AutomationDirect Productivity Suite project: SD_Homing_Sensor (software 3.9.0 (26))
author: matt_cmelko
Rung notation: left to right = series (deeper-indented lines continue the line above), [a | b] = parallel branches, -- = plain wire, BOX.Pin = further input of the box above; 'quoted' = tag name, ? = field left empty; instruction and field names as stored in the project; options that are off are not listed.

HARDWARE
  EtherNet/IP device: Generic Client "ClearLink"
  Base 1 (1 slots)
    slot 0: P1-540

STRUCTURES
STRUCTURE 'Step Motor Status'
  AtTargetPosition : Boolean, strLength=15
  StepsActive : Boolean, strLength=15
  AtTargetVelocity : Boolean, strLength=15
  MoveDirection : Boolean, strLength=15
  InPosLimit : Boolean, strLength=15
  InNegLimit : Boolean, strLength=15
  InESTOPSensor : Boolean, strLength=15
  InHomeSensor : Boolean, strLength=15
  Homing : Boolean, strLength=15
  MotorInFault : Boolean, strLength=15
  Enabled : Boolean, strLength=15
  AtSoftLimits : Boolean, strLength=15
  PositionMove : Boolean, strLength=15
  HasHomed : Boolean, strLength=15
  HLFBON : Boolean, strLength=15
  HasTorqueMeasurement : Boolean, strLength=15
  ReadyToHome : Boolean, strLength=15
  ShutdownPresent : Boolean, strLength=15
  AddToPosAck : Boolean, strLength=15
  LoadPositionAck : Boolean, strLength=15
  LoadVelAck : Boolean, strLength=15
  ClearMotorFaultAck : Boolean, strLength=15
STRUCTURE 'Step Motor Shutdown'
  MCShutdownsPresent : Boolean, strLength=15
  MCPosLimit : Boolean, strLength=15
  MCNegLimit : Boolean, strLength=15
  MCSensorESTOP : Boolean, strLength=15
  MCSWESTOP : Boolean, strLength=15
  MCDisabled : Boolean, strLength=15
  MCSoftLimits : Boolean, strLength=15
  MCFollowerAxisFault : Boolean, strLength=15
  MCCmndFollowing : Boolean, strLength=15
  MCHomingNotReady : Boolean, strLength=15
  MotorFault : Boolean, strLength=15
  Reserved : Boolean, strLength=15
STRUCTURE 'Step Motor Output Reg'
  Enable : Boolean, strLength=15
  AbsolutelMoveFlag : Boolean, strLength=15
  HomingFlag : Boolean, strLength=15
  LoadPositionData : Boolean, strLength=15
  LoadVelocityData : Boolean, strLength=15
  SWESTOP : Boolean, strLength=15
  ClearAlerts : Boolean, strLength=15
  ClearMotorFault : Boolean, strLength=15
STRUCTURE 'Step and Dir Input Data'
  CommandedPosition : Array of Int32, dimensions=1, strLength=15
  CommandedVelocity : Array of Int32, dimensions=1, strLength=15
  TargetPosition : Array of Int32, dimensions=1, strLength=15
  TargetVelocity : Array of Int32, dimensions=1, strLength=15
  CapturedPosition : Array of Int32, dimensions=1, strLength=15
  MeasuredTorque : Array of Float32, dimensions=1, strLength=15
  MotorStatus : Step Motor Status, strLength=15
  MotorShutdowns : Step Motor Shutdown, strLength=15
STRUCTURE 'Step and Dir Output Data'
  MoveDistance : Array of Int32, dimensions=1, strLength=15
  VelocityLimit : Array of Int32, dimensions=1, strLength=15
  AccelerationLimit : Array of Int32, dimensions=1, strLength=15
  DecelerationLimit : Array of Int32, dimensions=1, strLength=15
  JogVelocity : Array of Int32, dimensions=1, strLength=15
  AddToPosition : Array of Int32, dimensions=1, strLength=15
  OutputReg : Step Motor Output Reg, strLength=15
STRUCTURE EncoderInputData
  PositionValue : Array of Int32, dimensions=1, strLength=15
  VelocityValue : Array of Int32, dimensions=1, strLength=15
  IndexPosition : Array of Int32, dimensions=1, strLength=15
  AlarmFlag : Array of Boolean, dimensions=1, strLength=15
  AddToPositionAck : Array of Boolean, dimensions=1, strLength=15
STRUCTURE 'IO Input Data'
  DIPValue : Array of Boolean, dimensions=13, strLength=15
  DIPStatus : Array of Boolean, dimensions=13, strLength=15
  AIPValue : Array of Int16, dimensions=4, strLength=15
  AIOPStatus : Array of Boolean, dimensions=5, strLength=15
  DOPStatus : Array of Boolean, dimensions=6, strLength=15
  CCIOInputValue : Array of Boolean, dimensions=64, strLength=15
  CCIOStatus : Array of Boolean, dimensions=64, strLength=15
  CCIOBoardCount : Array of Uint8, dimensions=1, strLength=15
STRUCTURE 'IO Output Data'
  AOPValue : Array of Int16, dimensions=1, strLength=15
  DOPValue : Array of Boolean, dimensions=6, strLength=15
  DOPPWM : Array of Uint8, dimensions=6, strLength=15
  CCIOOutputValue : Array of Boolean, dimensions=64, strLength=15
STRUCTURE 'ASCII INPUT'
  Status : Array of Boolean, dimensions=8, strLength=15
  OutputCharCount : Array of Int32, dimensions=1, strLength=15
  InputCharCount : Array of Int32, dimensions=1, strLength=15
  OutputSeqAck : Array of Int32, dimensions=1, strLength=15
  InputSize : Array of Int32, dimensions=1, strLength=15
  InputSeq : Array of Int32, dimensions=1, strLength=15
  InputData : Array of Uint8, dimensions=128, strLength=15
STRUCTURE 'ASCII Output'
  Config : Array of Boolean, dimensions=19, strLength=15
  InputSeqAck : Array of Int32, dimensions=1, strLength=15
  OutputSize : Array of Int32, dimensions=1, strLength=15
  OutputSeq : Array of Int32, dimensions=1, strLength=15
  OutputData : Array of Uint8, dimensions=128, strLength=15
STRUCTURE EncoderOutputData
  AddToPosn : Array of Int32, dimensions=1, strLength=15
STRUCTURE 'IO Output Data_1'
  AOPValue : Array of Int16, dimensions=1, strLength=15
  DOPValue : Array of Boolean, dimensions=6, strLength=15
  DOPPWM : Array of Uint8, dimensions=8, strLength=15
  CCIOOutputValue : Array of Boolean, dimensions=64, strLength=15

TAGS  (name : type @system ID = initial value)
  ClearLinkConnectionEnable : Boolean @C-000001
  CLstatusdescription : String(32) @STR-000001
  OutputData : Array[496] of Uint8 @AR1US8-000013
  InputData : Array[496] of Uint8 @AR1US8-000023
  'ClearLink Encoder Output' : EncoderOutputData @USTRUC-000068
  'ClearLink Encoder Input' : EncoderInputData @USTRUC-000069
  'ClearLink Motor0 Output' : Step and Dir Output Data @USTRUC-000070
  'ClearLink Motor1 Output' : Step and Dir Output Data @USTRUC-000072
  'ClearLink Motor2 Output' : Step and Dir Output Data @USTRUC-000074
  'ClearLink Motor3 Output' : Step and Dir Output Data @USTRUC-000076
  'ClearLink Motor3 Input' : Step and Dir Input Data @USTRUC-000078
  'ClearLink Motor2 Input' : Step and Dir Input Data @USTRUC-000081
  'ClearLink Motor1 Input' : Step and Dir Input Data @USTRUC-000084
  'ClearLink Motor0 Input' : Step and Dir Input Data @USTRUC-000087
  'ClearLink IO Input' : IO Input Data @USTRUC-000209
  'ClearLink IO Output' : IO Output Data @USTRUC-000210
  floatPlaceholder : Array[4] of Int32 @AR1S32-000267
  'ClearLink ASCII Input' : ASCII INPUT @USTRUC-000211
  'ClearLink ASCII Output' : ASCII Output @USTRUC-000212
  Begin_Homing : Boolean @C-000842
  Zero_Posn_After_Offset_Move : Boolean @C-000843
  ZeroPosnOneShot : Boolean @C-000845
  ClearLinkConnectionOnline : Boolean @C-000846

TASK 'Main Task'  (Run Every Scan)
// Program Name: SD_Homing_Sensor
// Program Description: This program is used to execute hardstop homing move and an offset move with a ClearPath-SD servo.
// See ladder comments below for descriptions on interacting with this example.
// Motor Required: One ClearPath-SD (Step & Direction) motor connected to ClearLink at connector M-0.
// Sensor Required: This example has been written to use a digital home sensor. Use a normally closed switch or NPN sensor wired to ClearLink's DI-6 input.
// Software Used: Productivity Suite (Version 3.9.0 was used to create this example).
// Controller Used: P1-540 was used to create this example.
// *******************************************************************************************************************************************************************************************
// BEFORE RUNNING THIS EXAMPLE, your ClearPath-SD motor must first be configured in MSP (ClearPath Motor Setup Program). See the ClearLink Software Object Data Reference for motor setup and configuration instructions: https://www.teknic.com/files/downloads/clearlink_ethernet-ip_object_reference.pdf.
// ***IMPORTANT*** FAILURE TO PROPERLY TUNE AND CONFIGURE YOUR CLEARPATH MOTOR BEFORE USE MAY RESULT IN UNEXPECTED MOTION, OR NO
// MOTION.
// *******************************************************************************************************************************************************************************************
// This example uses non-default ClearLink Configuration Data. Bit 0 of the Motor0Config register has been set to enable homing. Motor 0 Home Sensor has been set to 6, corresponding to input DI-6.
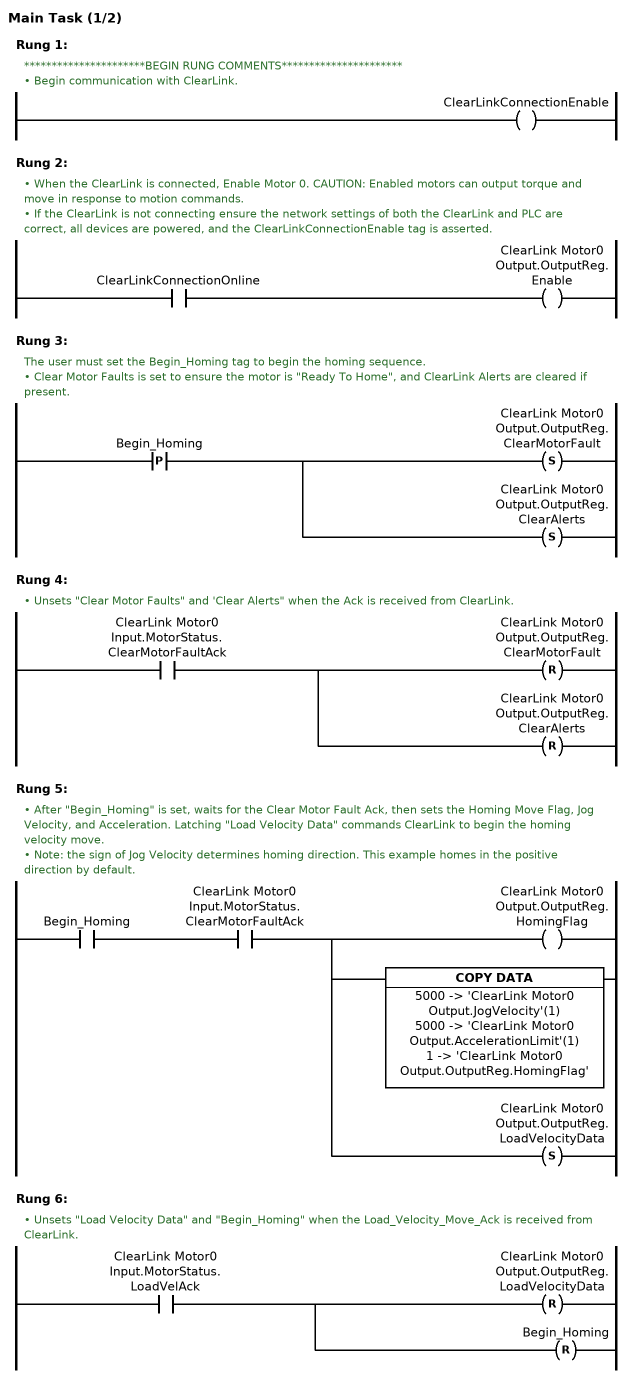
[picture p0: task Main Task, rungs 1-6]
Rung 1:
  // **********************BEGIN RUNG COMMENTS**********************
  // • Begin communication with ClearLink.
  OUT(ClearLinkConnectionEnable)
Rung 2:
  // • When the ClearLink is connected, Enable Motor 0. CAUTION: Enabled motors can output torque and move in response to motion commands.
  // • If the ClearLink is not connecting ensure the network settings of both the ClearLink and PLC are correct, all devices are powered, and the ClearLinkConnectionEnable tag is asserted.
  NO(ClearLinkConnectionOnline) OUT('ClearLink Motor0 Output.OutputReg.Enable')
Rung 3:
  // The user must set the Begin_Homing tag to begin the homing sequence.
  // • Clear Motor Faults is set to ensure the motor is "Ready To Home", and ClearLink Alerts are cleared if present.
  NOE(Begin_Homing, rising)
    [SET('ClearLink Motor0 Output.OutputReg.ClearMotorFault') | SET('ClearLink Motor0 Output.OutputReg.ClearAlerts')]
Rung 4:
  // • Unsets "Clear Motor Faults" and 'Clear Alerts" when the Ack is received from ClearLink.
  NO('ClearLink Motor0 Input.MotorStatus.ClearMotorFaultAck')
    [RST('ClearLink Motor0 Output.OutputReg.ClearMotorFault') | RST('ClearLink Motor0 Output.OutputReg.ClearAlerts')]
Rung 5:
  // • After "Begin_Homing" is set, waits for the Clear Motor Fault Ack, then sets the Homing Move Flag, Jog Velocity, and Acceleration. Latching "Load Velocity Data" commands ClearLink to begin the homing velocity move.
  // • Note: the sign of Jog Velocity determines homing direction. This example homes in the positive direction by default.
  NO(Begin_Homing) NO('ClearLink Motor0 Input.MotorStatus.ClearMotorFaultAck')
    [ OUT('ClearLink Motor0 Output.OutputReg.HomingFlag')
    | CPY(5000 -> 'ClearLink Motor0 Output.JogVelocity'(1), 5000 -> 'ClearLink Motor0 Output.AccelerationLimit'(1), 1 -> 'ClearLink Motor0 Output.OutputReg.HomingFlag')
    | SET('ClearLink Motor0 Output.OutputReg.LoadVelocityData') ]
Rung 6:
  // • Unsets "Load Velocity Data" and "Begin_Homing" when the Load_Velocity_Move_Ack is received from ClearLink.
  NO('ClearLink Motor0 Input.MotorStatus.LoadVelAck')
    [RST('ClearLink Motor0 Output.OutputReg.LoadVelocityData') | RST(Begin_Homing)]
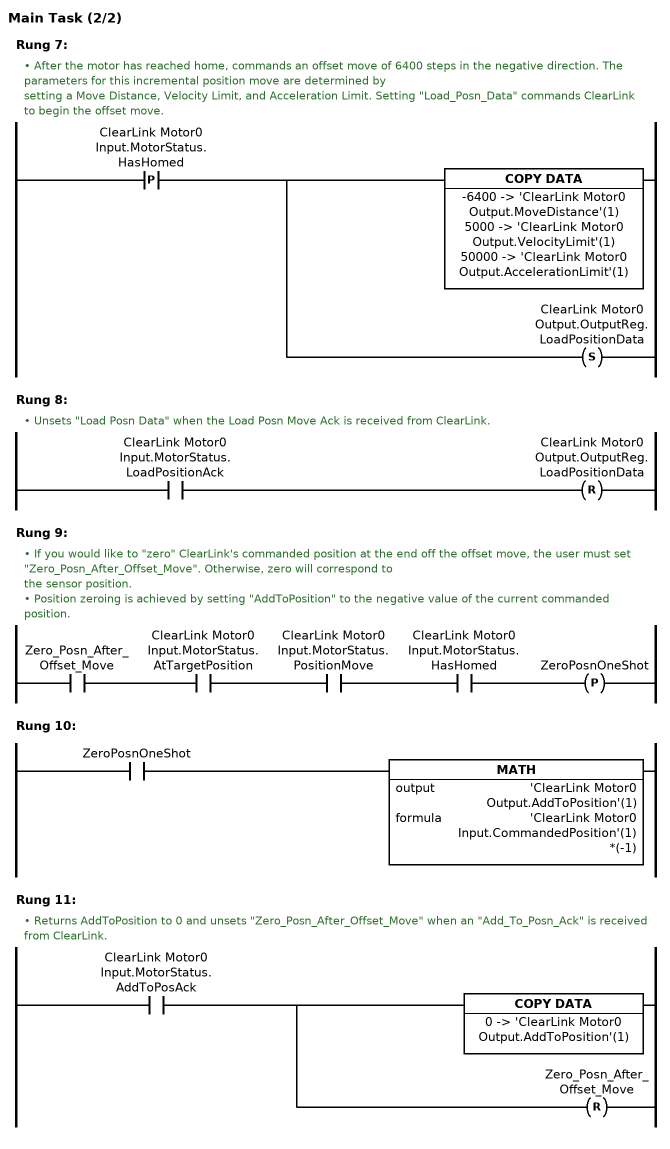
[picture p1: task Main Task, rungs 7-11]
Rung 7:
  // • After the motor has reached home, commands an offset move of 6400 steps in the negative direction. The parameters for this incremental position move are determined by
  // setting a Move Distance, Velocity Limit, and Acceleration Limit. Setting "Load_Posn_Data" commands ClearLink to begin the offset move.
  NOE('ClearLink Motor0 Input.MotorStatus.HasHomed', rising)
    [ CPY(-6400 -> 'ClearLink Motor0 Output.MoveDistance'(1), 5000 -> 'ClearLink Motor0 Output.VelocityLimit'(1), 50000 -> 'ClearLink Motor0 Output.AccelerationLimit'(1))
    | SET('ClearLink Motor0 Output.OutputReg.LoadPositionData') ]
Rung 8:
  // • Unsets "Load Posn Data" when the Load Posn Move Ack is received from ClearLink.
  NO('ClearLink Motor0 Input.MotorStatus.LoadPositionAck') RST('ClearLink Motor0 Output.OutputReg.LoadPositionData')
Rung 9:
  // • If you would like to "zero" ClearLink's commanded position at the end off the offset move, the user must set "Zero_Posn_After_Offset_Move". Otherwise, zero will correspond to
  // the sensor position.
  // • Position zeroing is achieved by setting "AddToPosition" to the negative value of the current commanded position.
  NO(Zero_Posn_After_Offset_Move) NO('ClearLink Motor0 Input.MotorStatus.AtTargetPosition')
    NO('ClearLink Motor0 Input.MotorStatus.PositionMove') NO('ClearLink Motor0 Input.MotorStatus.HasHomed')
    OUT(ZeroPosnOneShot, oneShot)
Rung 10:
  NO(ZeroPosnOneShot)
    MATH('ClearLink Motor0 Output.AddToPosition'(1) = 'ClearLink Motor0 Input.CommandedPosition'(1) *(-1))
Rung 11:
  // • Returns AddToPosition to 0 and unsets "Zero_Posn_After_Offset_Move" when an "Add_To_Posn_Ack" is received from ClearLink.
  NO('ClearLink Motor0 Input.MotorStatus.AddToPosAck')
    [CPY(0 -> 'ClearLink Motor0 Output.AddToPosition'(1)) | RST(Zero_Posn_After_Offset_Move)]

TASK 'Data Sorting - IO'  (Run Every Scan)
// Copies assembly data to/from named controller tags. Do not edit.
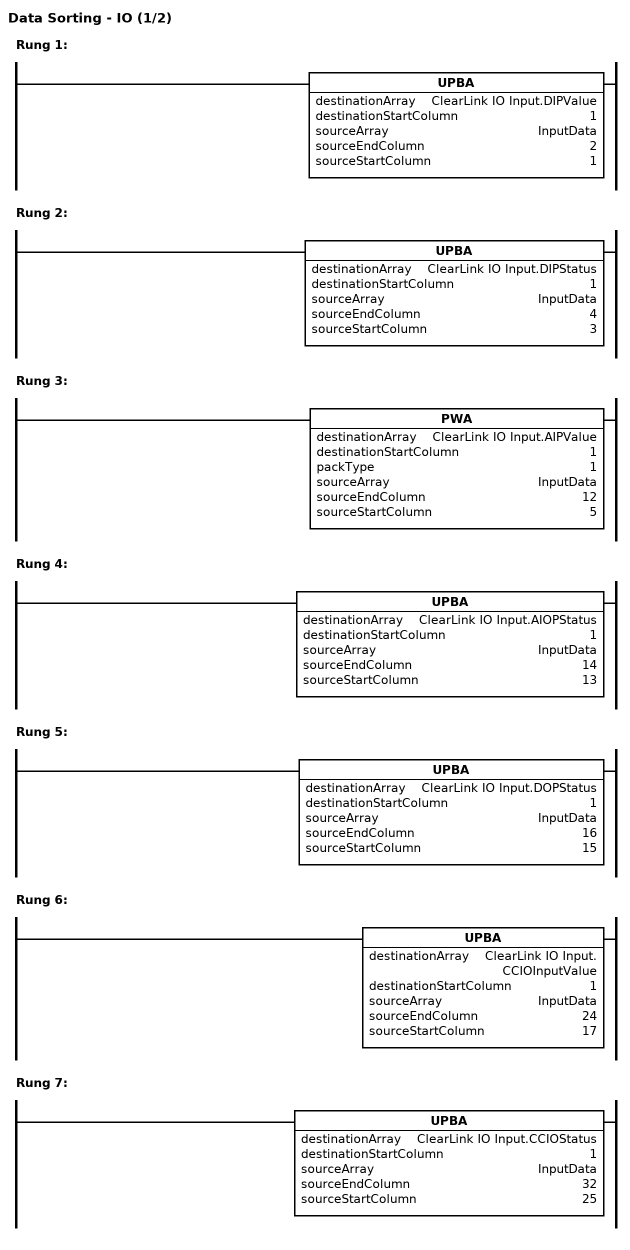
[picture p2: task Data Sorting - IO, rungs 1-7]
Rung 1:
  UPBA(destinationArray='ClearLink IO Input.DIPValue', destinationStartColumn=1, sourceArray=InputData, sourceEndColumn=2, sourceStartColumn=1)
Rung 2:
  UPBA(destinationArray='ClearLink IO Input.DIPStatus', destinationStartColumn=1, sourceArray=InputData, sourceEndColumn=4, sourceStartColumn=3)
Rung 3:
  PWA(destinationArray='ClearLink IO Input.AIPValue', destinationStartColumn=1, packType=1, sourceArray=InputData, sourceEndColumn=12, sourceStartColumn=5)
Rung 4:
  UPBA(destinationArray='ClearLink IO Input.AIOPStatus', destinationStartColumn=1, sourceArray=InputData, sourceEndColumn=14, sourceStartColumn=13)
Rung 5:
  UPBA(destinationArray='ClearLink IO Input.DOPStatus', destinationStartColumn=1, sourceArray=InputData, sourceEndColumn=16, sourceStartColumn=15)
Rung 6:
  UPBA(destinationArray='ClearLink IO Input.CCIOInputValue', destinationStartColumn=1, sourceArray=InputData, sourceEndColumn=24, sourceStartColumn=17)
Rung 7:
  UPBA(destinationArray='ClearLink IO Input.CCIOStatus', destinationStartColumn=1, sourceArray=InputData, sourceEndColumn=32, sourceStartColumn=25)
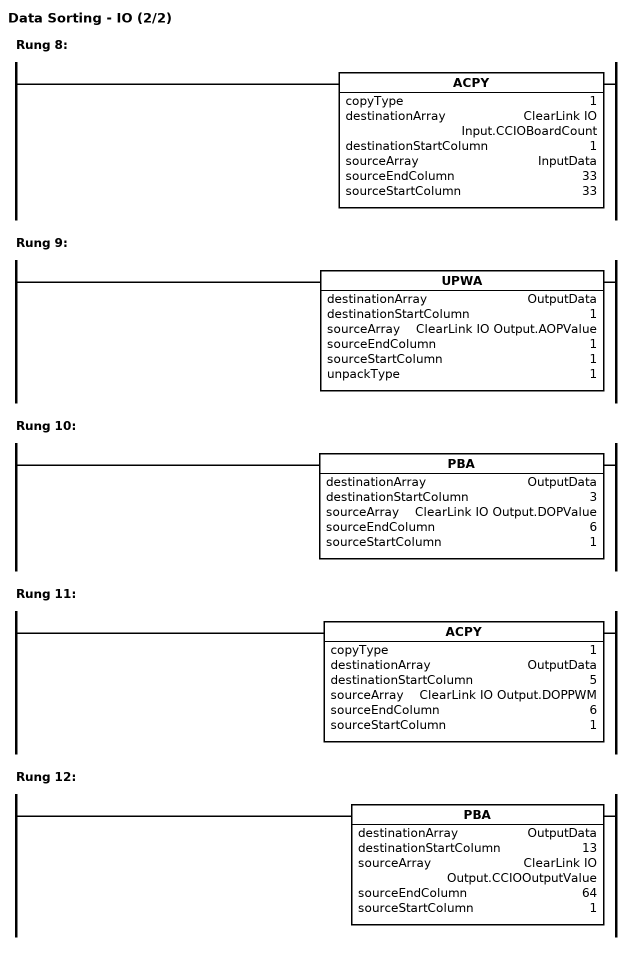
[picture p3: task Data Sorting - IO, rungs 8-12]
Rung 8:
  ACPY(copyType=1, destinationArray='ClearLink IO Input.CCIOBoardCount', destinationStartColumn=1, sourceArray=InputData, sourceEndColumn=33, sourceStartColumn=33)
Rung 9:
  UPWA(destinationArray=OutputData, destinationStartColumn=1, sourceArray='ClearLink IO Output.AOPValue', sourceEndColumn=1, sourceStartColumn=1, unpackType=1)
Rung 10:
  PBA(destinationArray=OutputData, destinationStartColumn=3, sourceArray='ClearLink IO Output.DOPValue', sourceEndColumn=6, sourceStartColumn=1)
Rung 11:
  ACPY(copyType=1, destinationArray=OutputData, destinationStartColumn=5, sourceArray='ClearLink IO Output.DOPPWM', sourceEndColumn=6, sourceStartColumn=1)
Rung 12:
  PBA(destinationArray=OutputData, destinationStartColumn=13, sourceArray='ClearLink IO Output.CCIOOutputValue', sourceEndColumn=64, sourceStartColumn=1)

TASK 'Data Sorting - Encoder'  (Run Every Scan)
// Copies assembly data to/from named controller tags. Do not edit.
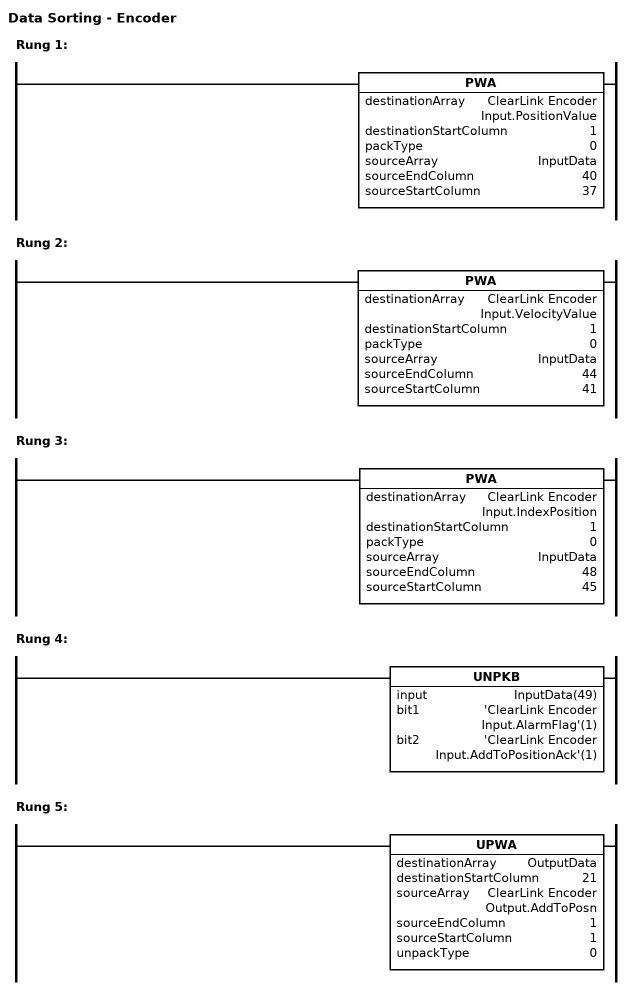
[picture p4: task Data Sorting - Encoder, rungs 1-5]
Rung 1:
  PWA(destinationArray='ClearLink Encoder Input.PositionValue', destinationStartColumn=1, packType=0, sourceArray=InputData, sourceEndColumn=40, sourceStartColumn=37)
Rung 2:
  PWA(destinationArray='ClearLink Encoder Input.VelocityValue', destinationStartColumn=1, packType=0, sourceArray=InputData, sourceEndColumn=44, sourceStartColumn=41)
Rung 3:
  PWA(destinationArray='ClearLink Encoder Input.IndexPosition', destinationStartColumn=1, packType=0, sourceArray=InputData, sourceEndColumn=48, sourceStartColumn=45)
Rung 4:
  UNPKB(input=InputData(49), bit1='ClearLink Encoder Input.AlarmFlag'(1), bit2='ClearLink Encoder Input.AddToPositionAck'(1))
Rung 5:
  UPWA(destinationArray=OutputData, destinationStartColumn=21, sourceArray='ClearLink Encoder Output.AddToPosn', sourceEndColumn=1, sourceStartColumn=1, unpackType=0)

TASK 'Data Sorting - Motor0'  (Run Every Scan)
// Copies assembly data to/from named controller tags. Do not edit.
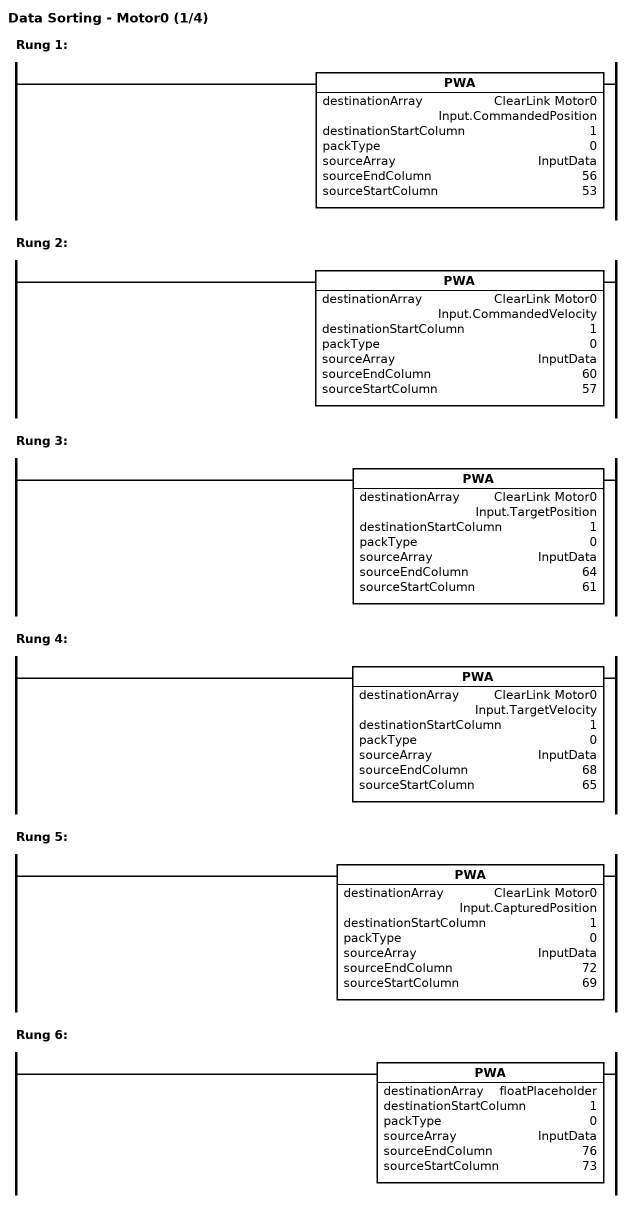
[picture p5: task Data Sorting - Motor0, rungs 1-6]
Rung 1:
  PWA(destinationArray='ClearLink Motor0 Input.CommandedPosition', destinationStartColumn=1, packType=0, sourceArray=InputData, sourceEndColumn=56, sourceStartColumn=53)
Rung 2:
  PWA(destinationArray='ClearLink Motor0 Input.CommandedVelocity', destinationStartColumn=1, packType=0, sourceArray=InputData, sourceEndColumn=60, sourceStartColumn=57)
Rung 3:
  PWA(destinationArray='ClearLink Motor0 Input.TargetPosition', destinationStartColumn=1, packType=0, sourceArray=InputData, sourceEndColumn=64, sourceStartColumn=61)
Rung 4:
  PWA(destinationArray='ClearLink Motor0 Input.TargetVelocity', destinationStartColumn=1, packType=0, sourceArray=InputData, sourceEndColumn=68, sourceStartColumn=65)
Rung 5:
  PWA(destinationArray='ClearLink Motor0 Input.CapturedPosition', destinationStartColumn=1, packType=0, sourceArray=InputData, sourceEndColumn=72, sourceStartColumn=69)
Rung 6:
  PWA(destinationArray=floatPlaceholder, destinationStartColumn=1, packType=0, sourceArray=InputData, sourceEndColumn=76, sourceStartColumn=73)
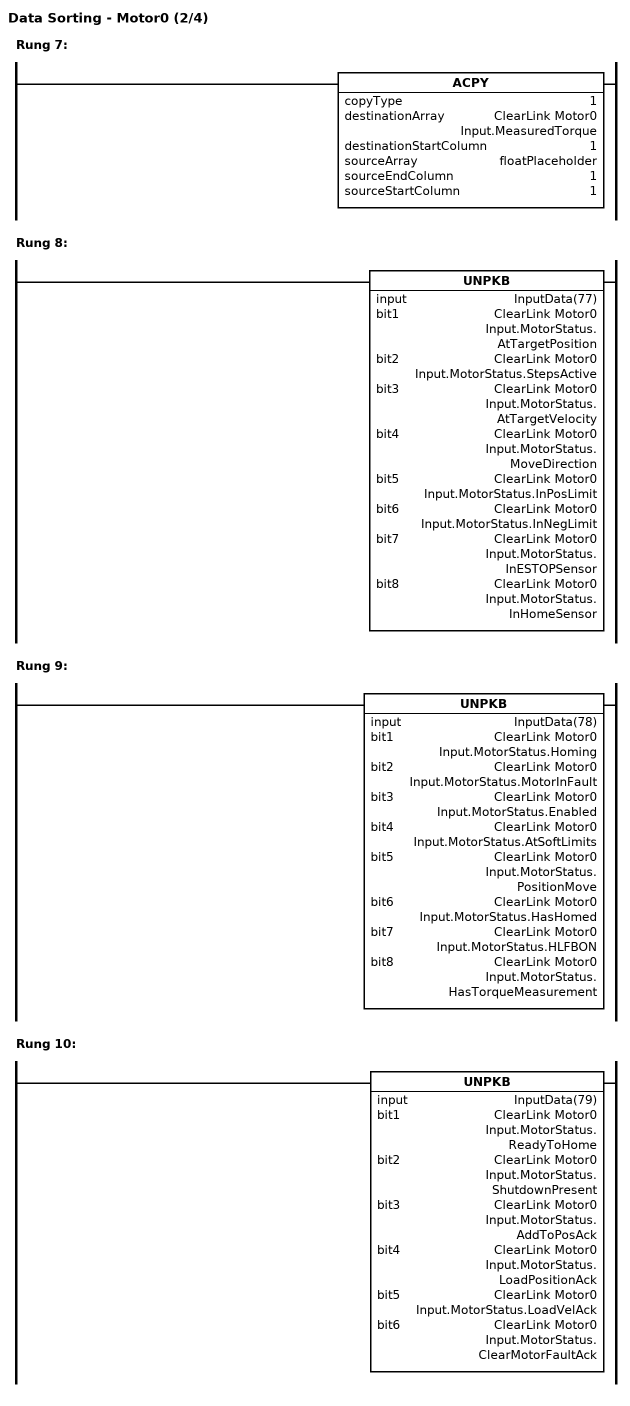
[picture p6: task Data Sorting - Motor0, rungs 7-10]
Rung 7:
  ACPY(copyType=1, destinationArray='ClearLink Motor0 Input.MeasuredTorque', destinationStartColumn=1, sourceArray=floatPlaceholder, sourceEndColumn=1, sourceStartColumn=1)
Rung 8:
  UNPKB(input=InputData(77), bit1='ClearLink Motor0 Input.MotorStatus.AtTargetPosition', bit2='ClearLink Motor0 Input.MotorStatus.StepsActive', bit3='ClearLink Motor0 Input.MotorStatus.AtTargetVelocity', bit4='ClearLink Motor0 Input.MotorStatus.MoveDirection', bit5='ClearLink Motor0 Input.MotorStatus.InPosLimit', bit6='ClearLink Motor0 Input.MotorStatus.InNegLimit', bit7='ClearLink Motor0 Input.MotorStatus.InESTOPSensor', bit8='ClearLink Motor0 Input.MotorStatus.InHomeSensor')
Rung 9:
  UNPKB(input=InputData(78), bit1='ClearLink Motor0 Input.MotorStatus.Homing', bit2='ClearLink Motor0 Input.MotorStatus.MotorInFault', bit3='ClearLink Motor0 Input.MotorStatus.Enabled', bit4='ClearLink Motor0 Input.MotorStatus.AtSoftLimits', bit5='ClearLink Motor0 Input.MotorStatus.PositionMove', bit6='ClearLink Motor0 Input.MotorStatus.HasHomed', bit7='ClearLink Motor0 Input.MotorStatus.HLFBON', bit8='ClearLink Motor0 Input.MotorStatus.HasTorqueMeasurement')
Rung 10:
  UNPKB(input=InputData(79), bit1='ClearLink Motor0 Input.MotorStatus.ReadyToHome', bit2='ClearLink Motor0 Input.MotorStatus.ShutdownPresent', bit3='ClearLink Motor0 Input.MotorStatus.AddToPosAck', bit4='ClearLink Motor0 Input.MotorStatus.LoadPositionAck', bit5='ClearLink Motor0 Input.MotorStatus.LoadVelAck', bit6='ClearLink Motor0 Input.MotorStatus.ClearMotorFaultAck')
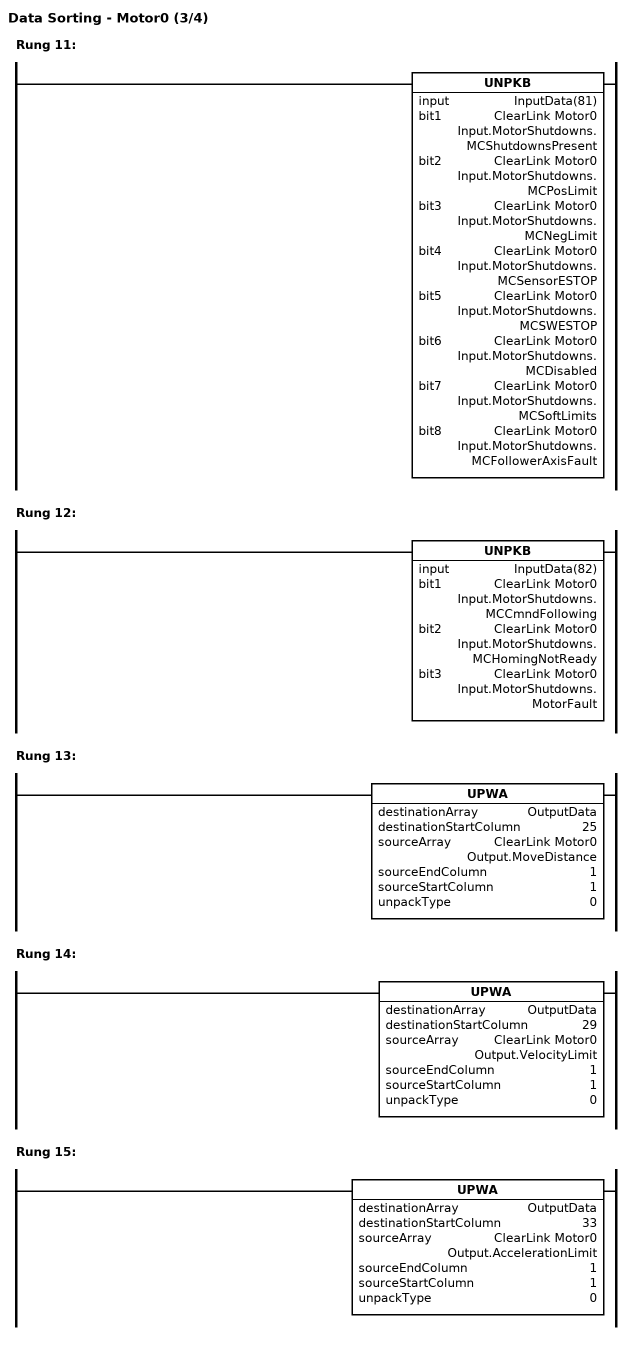
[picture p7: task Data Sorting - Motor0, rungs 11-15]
Rung 11:
  UNPKB(input=InputData(81), bit1='ClearLink Motor0 Input.MotorShutdowns.MCShutdownsPresent', bit2='ClearLink Motor0 Input.MotorShutdowns.MCPosLimit', bit3='ClearLink Motor0 Input.MotorShutdowns.MCNegLimit', bit4='ClearLink Motor0 Input.MotorShutdowns.MCSensorESTOP', bit5='ClearLink Motor0 Input.MotorShutdowns.MCSWESTOP', bit6='ClearLink Motor0 Input.MotorShutdowns.MCDisabled', bit7='ClearLink Motor0 Input.MotorShutdowns.MCSoftLimits', bit8='ClearLink Motor0 Input.MotorShutdowns.MCFollowerAxisFault')
Rung 12:
  UNPKB(input=InputData(82), bit1='ClearLink Motor0 Input.MotorShutdowns.MCCmndFollowing', bit2='ClearLink Motor0 Input.MotorShutdowns.MCHomingNotReady', bit3='ClearLink Motor0 Input.MotorShutdowns.MotorFault')
Rung 13:
  UPWA(destinationArray=OutputData, destinationStartColumn=25, sourceArray='ClearLink Motor0 Output.MoveDistance', sourceEndColumn=1, sourceStartColumn=1, unpackType=0)
Rung 14:
  UPWA(destinationArray=OutputData, destinationStartColumn=29, sourceArray='ClearLink Motor0 Output.VelocityLimit', sourceEndColumn=1, sourceStartColumn=1, unpackType=0)
Rung 15:
  UPWA(destinationArray=OutputData, destinationStartColumn=33, sourceArray='ClearLink Motor0 Output.AccelerationLimit', sourceEndColumn=1, sourceStartColumn=1, unpackType=0)
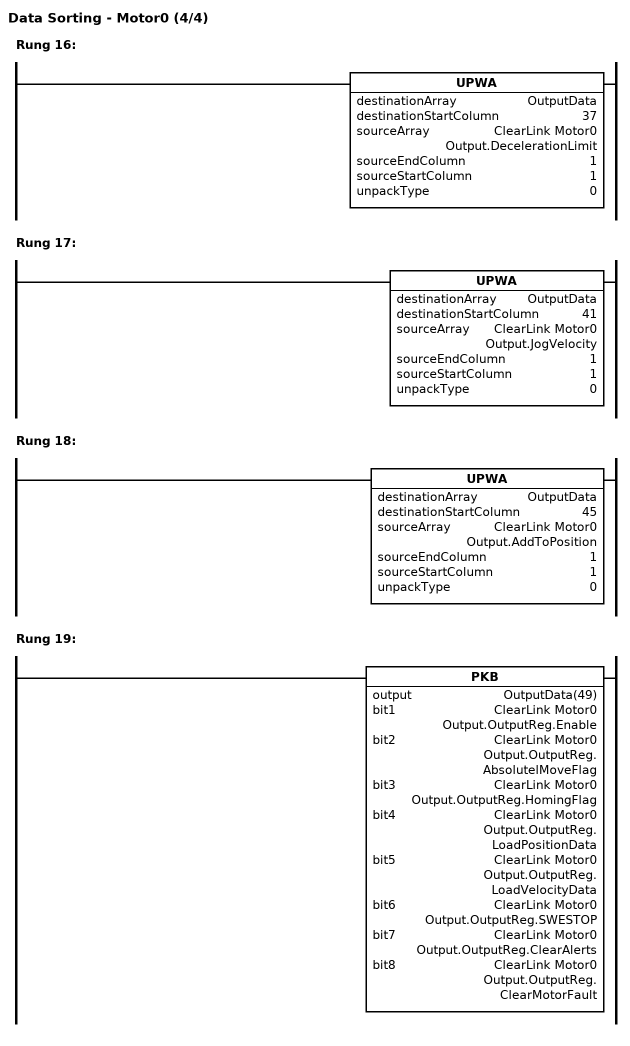
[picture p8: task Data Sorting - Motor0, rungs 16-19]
Rung 16:
  UPWA(destinationArray=OutputData, destinationStartColumn=37, sourceArray='ClearLink Motor0 Output.DecelerationLimit', sourceEndColumn=1, sourceStartColumn=1, unpackType=0)
Rung 17:
  UPWA(destinationArray=OutputData, destinationStartColumn=41, sourceArray='ClearLink Motor0 Output.JogVelocity', sourceEndColumn=1, sourceStartColumn=1, unpackType=0)
Rung 18:
  UPWA(destinationArray=OutputData, destinationStartColumn=45, sourceArray='ClearLink Motor0 Output.AddToPosition', sourceEndColumn=1, sourceStartColumn=1, unpackType=0)
Rung 19:
  PKB(output=OutputData(49), bit1='ClearLink Motor0 Output.OutputReg.Enable', bit2='ClearLink Motor0 Output.OutputReg.AbsolutelMoveFlag', bit3='ClearLink Motor0 Output.OutputReg.HomingFlag', bit4='ClearLink Motor0 Output.OutputReg.LoadPositionData', bit5='ClearLink Motor0 Output.OutputReg.LoadVelocityData', bit6='ClearLink Motor0 Output.OutputReg.SWESTOP', bit7='ClearLink Motor0 Output.OutputReg.ClearAlerts', bit8='ClearLink Motor0 Output.OutputReg.ClearMotorFault')

TASK 'Data Sorting - Motor1'  (Run Every Scan)
// Copies assembly data to/from named controller tags. Do not edit.
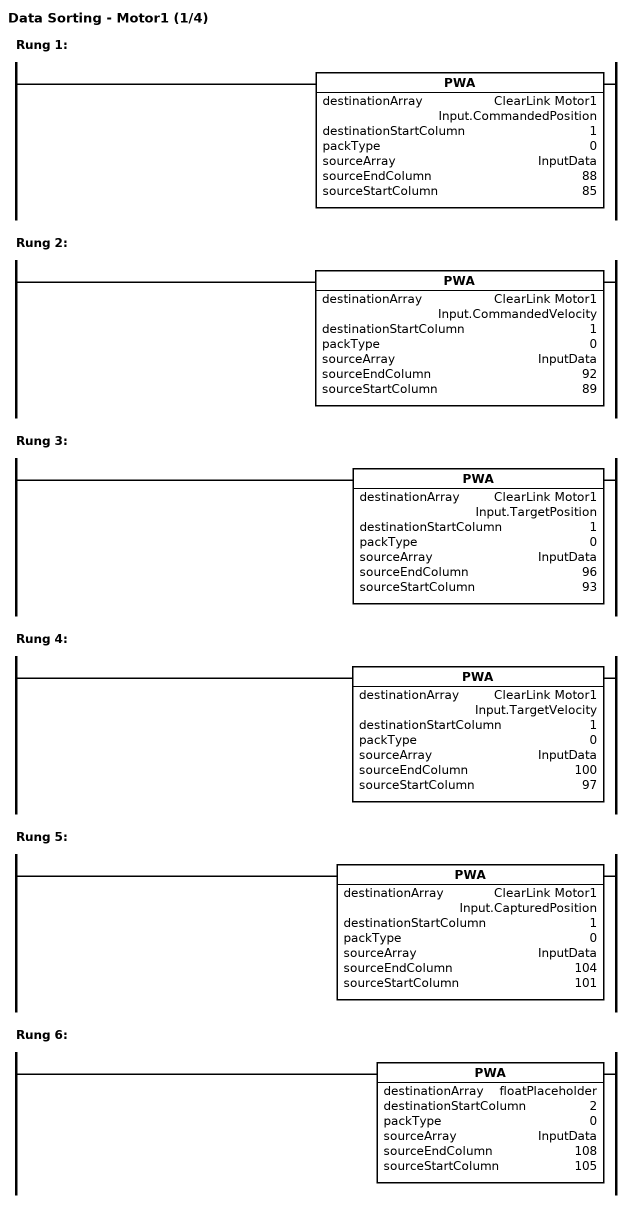
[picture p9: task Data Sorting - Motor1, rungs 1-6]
Rung 1:
  PWA(destinationArray='ClearLink Motor1 Input.CommandedPosition', destinationStartColumn=1, packType=0, sourceArray=InputData, sourceEndColumn=88, sourceStartColumn=85)
Rung 2:
  PWA(destinationArray='ClearLink Motor1 Input.CommandedVelocity', destinationStartColumn=1, packType=0, sourceArray=InputData, sourceEndColumn=92, sourceStartColumn=89)
Rung 3:
  PWA(destinationArray='ClearLink Motor1 Input.TargetPosition', destinationStartColumn=1, packType=0, sourceArray=InputData, sourceEndColumn=96, sourceStartColumn=93)
Rung 4:
  PWA(destinationArray='ClearLink Motor1 Input.TargetVelocity', destinationStartColumn=1, packType=0, sourceArray=InputData, sourceEndColumn=100, sourceStartColumn=97)
Rung 5:
  PWA(destinationArray='ClearLink Motor1 Input.CapturedPosition', destinationStartColumn=1, packType=0, sourceArray=InputData, sourceEndColumn=104, sourceStartColumn=101)
Rung 6:
  PWA(destinationArray=floatPlaceholder, destinationStartColumn=2, packType=0, sourceArray=InputData, sourceEndColumn=108, sourceStartColumn=105)
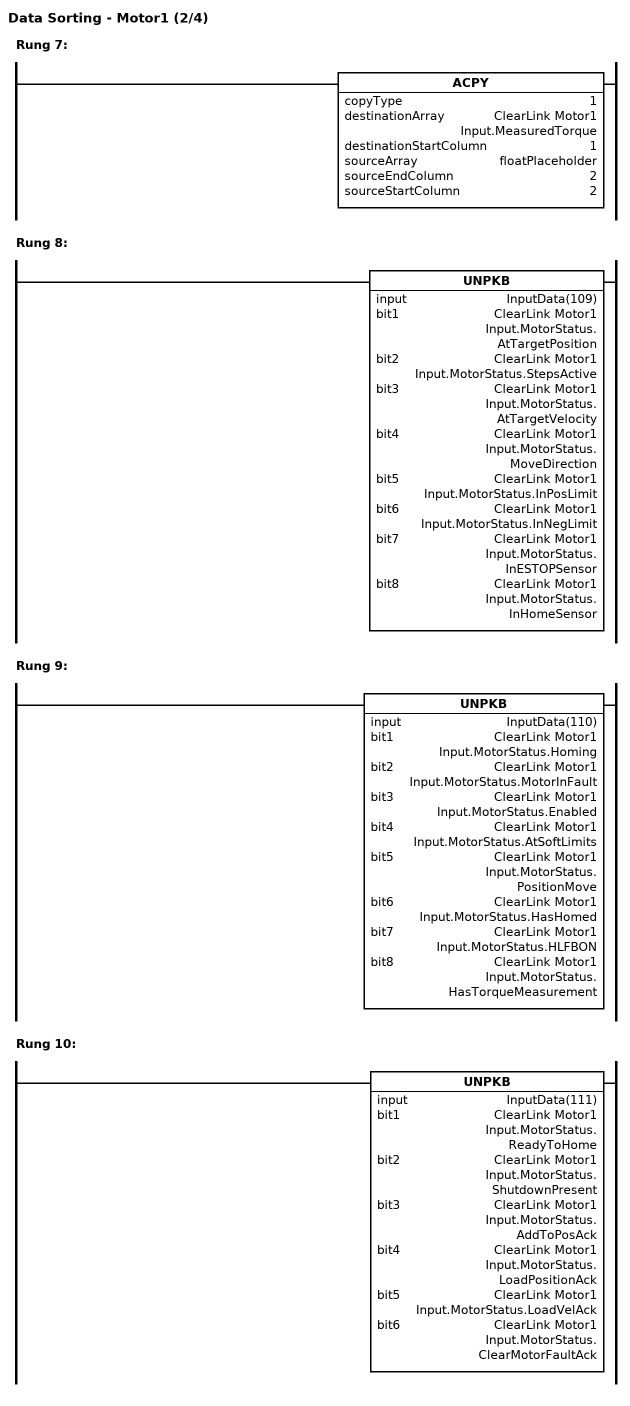
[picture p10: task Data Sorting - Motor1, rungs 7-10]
Rung 7:
  ACPY(copyType=1, destinationArray='ClearLink Motor1 Input.MeasuredTorque', destinationStartColumn=1, sourceArray=floatPlaceholder, sourceEndColumn=2, sourceStartColumn=2)
Rung 8:
  UNPKB(input=InputData(109), bit1='ClearLink Motor1 Input.MotorStatus.AtTargetPosition', bit2='ClearLink Motor1 Input.MotorStatus.StepsActive', bit3='ClearLink Motor1 Input.MotorStatus.AtTargetVelocity', bit4='ClearLink Motor1 Input.MotorStatus.MoveDirection', bit5='ClearLink Motor1 Input.MotorStatus.InPosLimit', bit6='ClearLink Motor1 Input.MotorStatus.InNegLimit', bit7='ClearLink Motor1 Input.MotorStatus.InESTOPSensor', bit8='ClearLink Motor1 Input.MotorStatus.InHomeSensor')
Rung 9:
  UNPKB(input=InputData(110), bit1='ClearLink Motor1 Input.MotorStatus.Homing', bit2='ClearLink Motor1 Input.MotorStatus.MotorInFault', bit3='ClearLink Motor1 Input.MotorStatus.Enabled', bit4='ClearLink Motor1 Input.MotorStatus.AtSoftLimits', bit5='ClearLink Motor1 Input.MotorStatus.PositionMove', bit6='ClearLink Motor1 Input.MotorStatus.HasHomed', bit7='ClearLink Motor1 Input.MotorStatus.HLFBON', bit8='ClearLink Motor1 Input.MotorStatus.HasTorqueMeasurement')
Rung 10:
  UNPKB(input=InputData(111), bit1='ClearLink Motor1 Input.MotorStatus.ReadyToHome', bit2='ClearLink Motor1 Input.MotorStatus.ShutdownPresent', bit3='ClearLink Motor1 Input.MotorStatus.AddToPosAck', bit4='ClearLink Motor1 Input.MotorStatus.LoadPositionAck', bit5='ClearLink Motor1 Input.MotorStatus.LoadVelAck', bit6='ClearLink Motor1 Input.MotorStatus.ClearMotorFaultAck')
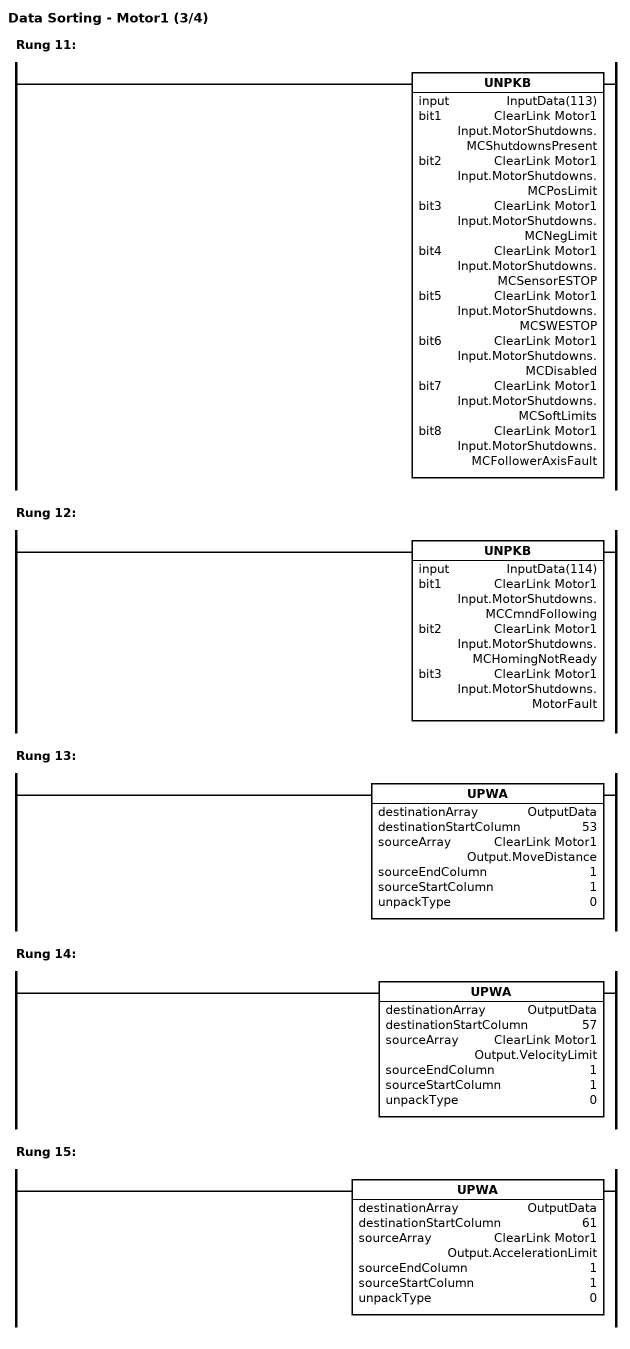
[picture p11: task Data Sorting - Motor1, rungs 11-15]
Rung 11:
  UNPKB(input=InputData(113), bit1='ClearLink Motor1 Input.MotorShutdowns.MCShutdownsPresent', bit2='ClearLink Motor1 Input.MotorShutdowns.MCPosLimit', bit3='ClearLink Motor1 Input.MotorShutdowns.MCNegLimit', bit4='ClearLink Motor1 Input.MotorShutdowns.MCSensorESTOP', bit5='ClearLink Motor1 Input.MotorShutdowns.MCSWESTOP', bit6='ClearLink Motor1 Input.MotorShutdowns.MCDisabled', bit7='ClearLink Motor1 Input.MotorShutdowns.MCSoftLimits', bit8='ClearLink Motor1 Input.MotorShutdowns.MCFollowerAxisFault')
Rung 12:
  UNPKB(input=InputData(114), bit1='ClearLink Motor1 Input.MotorShutdowns.MCCmndFollowing', bit2='ClearLink Motor1 Input.MotorShutdowns.MCHomingNotReady', bit3='ClearLink Motor1 Input.MotorShutdowns.MotorFault')
Rung 13:
  UPWA(destinationArray=OutputData, destinationStartColumn=53, sourceArray='ClearLink Motor1 Output.MoveDistance', sourceEndColumn=1, sourceStartColumn=1, unpackType=0)
Rung 14:
  UPWA(destinationArray=OutputData, destinationStartColumn=57, sourceArray='ClearLink Motor1 Output.VelocityLimit', sourceEndColumn=1, sourceStartColumn=1, unpackType=0)
Rung 15:
  UPWA(destinationArray=OutputData, destinationStartColumn=61, sourceArray='ClearLink Motor1 Output.AccelerationLimit', sourceEndColumn=1, sourceStartColumn=1, unpackType=0)
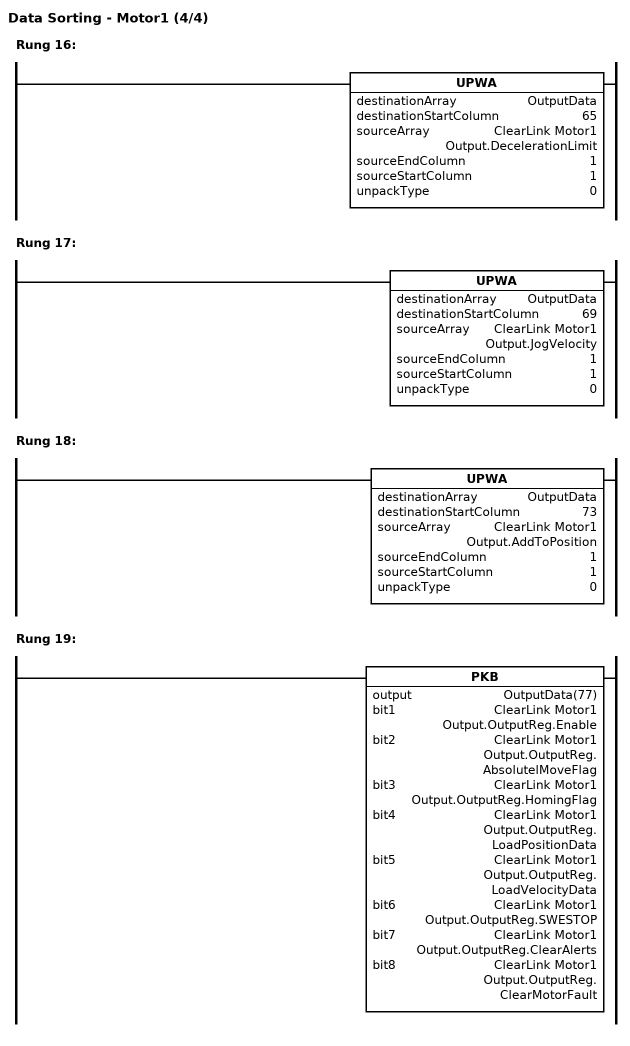
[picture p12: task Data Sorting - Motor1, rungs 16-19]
Rung 16:
  UPWA(destinationArray=OutputData, destinationStartColumn=65, sourceArray='ClearLink Motor1 Output.DecelerationLimit', sourceEndColumn=1, sourceStartColumn=1, unpackType=0)
Rung 17:
  UPWA(destinationArray=OutputData, destinationStartColumn=69, sourceArray='ClearLink Motor1 Output.JogVelocity', sourceEndColumn=1, sourceStartColumn=1, unpackType=0)
Rung 18:
  UPWA(destinationArray=OutputData, destinationStartColumn=73, sourceArray='ClearLink Motor1 Output.AddToPosition', sourceEndColumn=1, sourceStartColumn=1, unpackType=0)
Rung 19:
  PKB(output=OutputData(77), bit1='ClearLink Motor1 Output.OutputReg.Enable', bit2='ClearLink Motor1 Output.OutputReg.AbsolutelMoveFlag', bit3='ClearLink Motor1 Output.OutputReg.HomingFlag', bit4='ClearLink Motor1 Output.OutputReg.LoadPositionData', bit5='ClearLink Motor1 Output.OutputReg.LoadVelocityData', bit6='ClearLink Motor1 Output.OutputReg.SWESTOP', bit7='ClearLink Motor1 Output.OutputReg.ClearAlerts', bit8='ClearLink Motor1 Output.OutputReg.ClearMotorFault')

TASK 'Data Sorting - Motor2'  (Run Every Scan)
// Copies assembly data to/from named controller tags. Do not edit.
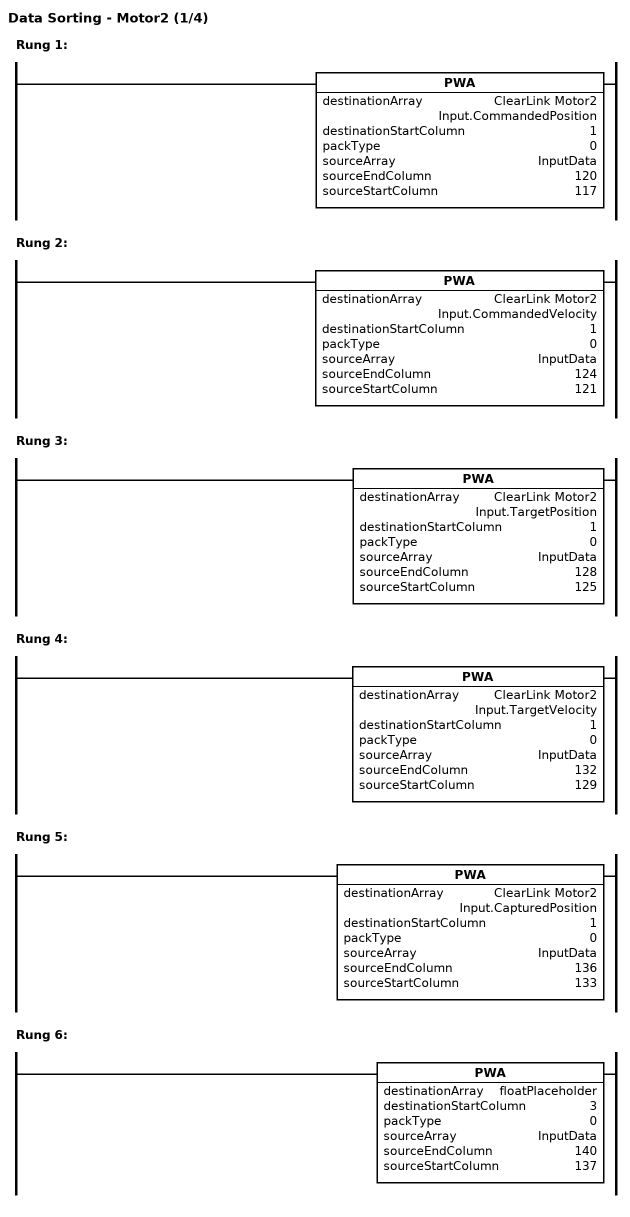
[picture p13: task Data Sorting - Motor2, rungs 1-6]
Rung 1:
  PWA(destinationArray='ClearLink Motor2 Input.CommandedPosition', destinationStartColumn=1, packType=0, sourceArray=InputData, sourceEndColumn=120, sourceStartColumn=117)
Rung 2:
  PWA(destinationArray='ClearLink Motor2 Input.CommandedVelocity', destinationStartColumn=1, packType=0, sourceArray=InputData, sourceEndColumn=124, sourceStartColumn=121)
Rung 3:
  PWA(destinationArray='ClearLink Motor2 Input.TargetPosition', destinationStartColumn=1, packType=0, sourceArray=InputData, sourceEndColumn=128, sourceStartColumn=125)
Rung 4:
  PWA(destinationArray='ClearLink Motor2 Input.TargetVelocity', destinationStartColumn=1, packType=0, sourceArray=InputData, sourceEndColumn=132, sourceStartColumn=129)
Rung 5:
  PWA(destinationArray='ClearLink Motor2 Input.CapturedPosition', destinationStartColumn=1, packType=0, sourceArray=InputData, sourceEndColumn=136, sourceStartColumn=133)
Rung 6:
  PWA(destinationArray=floatPlaceholder, destinationStartColumn=3, packType=0, sourceArray=InputData, sourceEndColumn=140, sourceStartColumn=137)
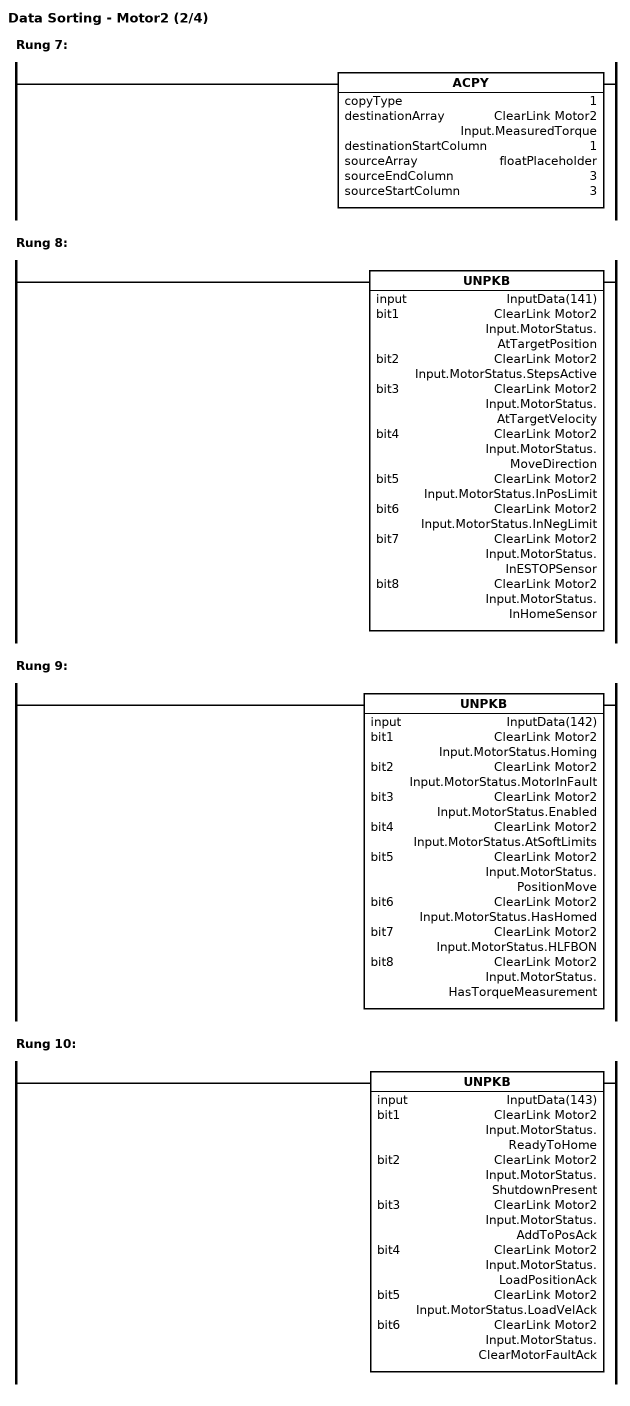
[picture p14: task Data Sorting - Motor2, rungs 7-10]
Rung 7:
  ACPY(copyType=1, destinationArray='ClearLink Motor2 Input.MeasuredTorque', destinationStartColumn=1, sourceArray=floatPlaceholder, sourceEndColumn=3, sourceStartColumn=3)
Rung 8:
  UNPKB(input=InputData(141), bit1='ClearLink Motor2 Input.MotorStatus.AtTargetPosition', bit2='ClearLink Motor2 Input.MotorStatus.StepsActive', bit3='ClearLink Motor2 Input.MotorStatus.AtTargetVelocity', bit4='ClearLink Motor2 Input.MotorStatus.MoveDirection', bit5='ClearLink Motor2 Input.MotorStatus.InPosLimit', bit6='ClearLink Motor2 Input.MotorStatus.InNegLimit', bit7='ClearLink Motor2 Input.MotorStatus.InESTOPSensor', bit8='ClearLink Motor2 Input.MotorStatus.InHomeSensor')
Rung 9:
  UNPKB(input=InputData(142), bit1='ClearLink Motor2 Input.MotorStatus.Homing', bit2='ClearLink Motor2 Input.MotorStatus.MotorInFault', bit3='ClearLink Motor2 Input.MotorStatus.Enabled', bit4='ClearLink Motor2 Input.MotorStatus.AtSoftLimits', bit5='ClearLink Motor2 Input.MotorStatus.PositionMove', bit6='ClearLink Motor2 Input.MotorStatus.HasHomed', bit7='ClearLink Motor2 Input.MotorStatus.HLFBON', bit8='ClearLink Motor2 Input.MotorStatus.HasTorqueMeasurement')
Rung 10:
  UNPKB(input=InputData(143), bit1='ClearLink Motor2 Input.MotorStatus.ReadyToHome', bit2='ClearLink Motor2 Input.MotorStatus.ShutdownPresent', bit3='ClearLink Motor2 Input.MotorStatus.AddToPosAck', bit4='ClearLink Motor2 Input.MotorStatus.LoadPositionAck', bit5='ClearLink Motor2 Input.MotorStatus.LoadVelAck', bit6='ClearLink Motor2 Input.MotorStatus.ClearMotorFaultAck')
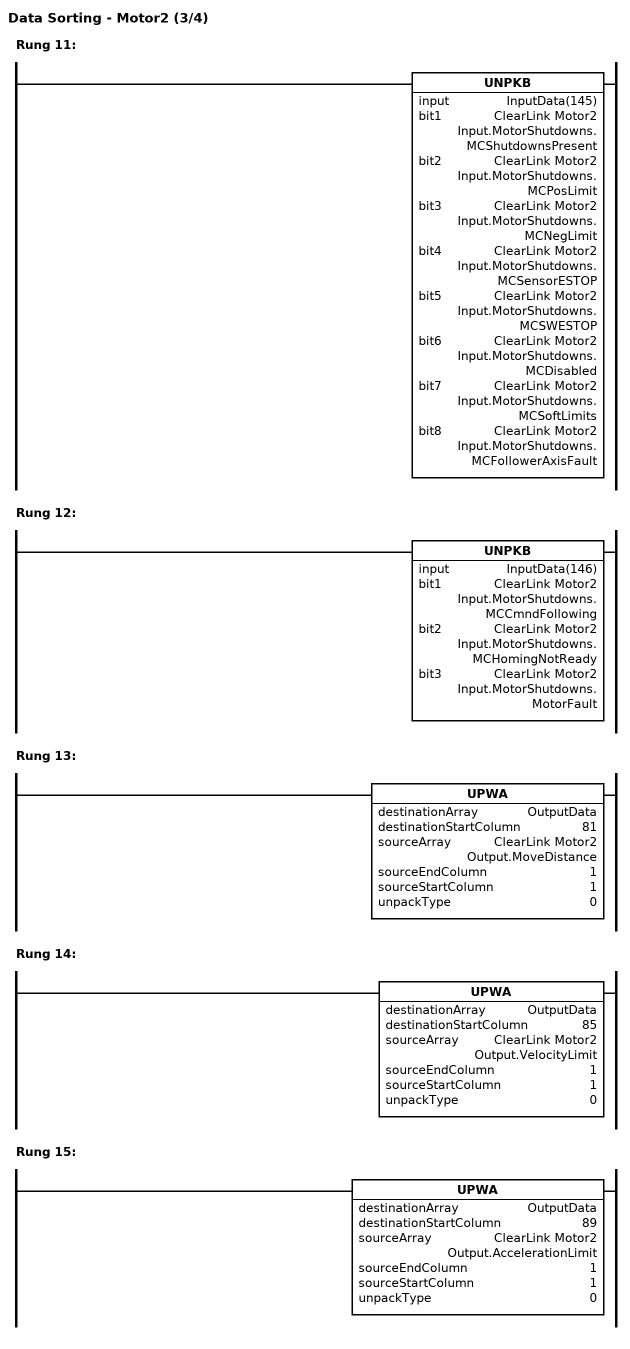
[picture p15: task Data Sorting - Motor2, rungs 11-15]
Rung 11:
  UNPKB(input=InputData(145), bit1='ClearLink Motor2 Input.MotorShutdowns.MCShutdownsPresent', bit2='ClearLink Motor2 Input.MotorShutdowns.MCPosLimit', bit3='ClearLink Motor2 Input.MotorShutdowns.MCNegLimit', bit4='ClearLink Motor2 Input.MotorShutdowns.MCSensorESTOP', bit5='ClearLink Motor2 Input.MotorShutdowns.MCSWESTOP', bit6='ClearLink Motor2 Input.MotorShutdowns.MCDisabled', bit7='ClearLink Motor2 Input.MotorShutdowns.MCSoftLimits', bit8='ClearLink Motor2 Input.MotorShutdowns.MCFollowerAxisFault')
Rung 12:
  UNPKB(input=InputData(146), bit1='ClearLink Motor2 Input.MotorShutdowns.MCCmndFollowing', bit2='ClearLink Motor2 Input.MotorShutdowns.MCHomingNotReady', bit3='ClearLink Motor2 Input.MotorShutdowns.MotorFault')
Rung 13:
  UPWA(destinationArray=OutputData, destinationStartColumn=81, sourceArray='ClearLink Motor2 Output.MoveDistance', sourceEndColumn=1, sourceStartColumn=1, unpackType=0)
Rung 14:
  UPWA(destinationArray=OutputData, destinationStartColumn=85, sourceArray='ClearLink Motor2 Output.VelocityLimit', sourceEndColumn=1, sourceStartColumn=1, unpackType=0)
Rung 15:
  UPWA(destinationArray=OutputData, destinationStartColumn=89, sourceArray='ClearLink Motor2 Output.AccelerationLimit', sourceEndColumn=1, sourceStartColumn=1, unpackType=0)
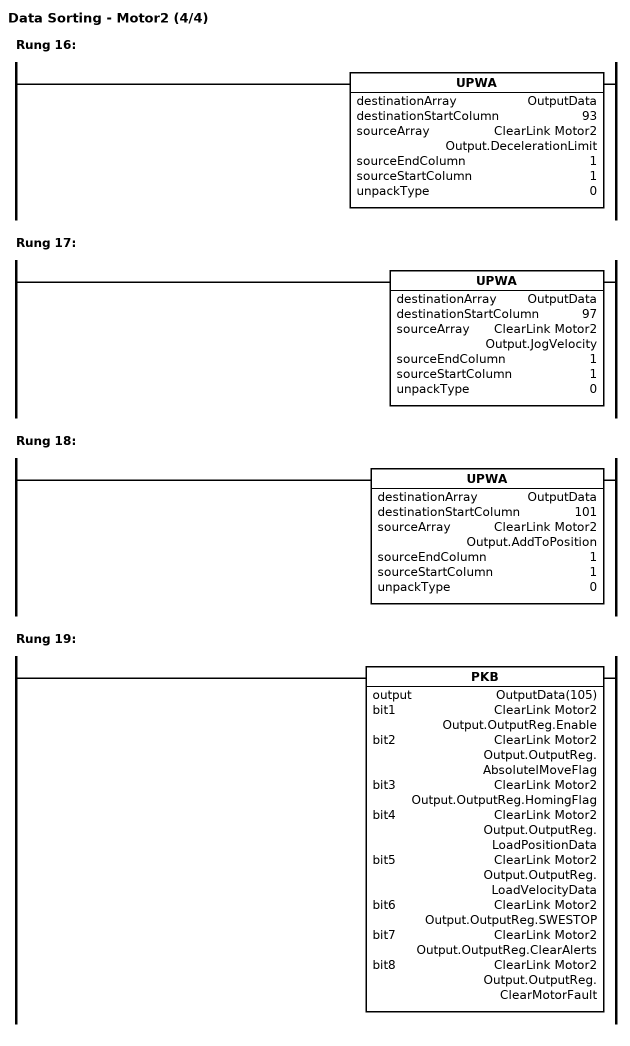
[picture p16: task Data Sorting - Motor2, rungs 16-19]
Rung 16:
  UPWA(destinationArray=OutputData, destinationStartColumn=93, sourceArray='ClearLink Motor2 Output.DecelerationLimit', sourceEndColumn=1, sourceStartColumn=1, unpackType=0)
Rung 17:
  UPWA(destinationArray=OutputData, destinationStartColumn=97, sourceArray='ClearLink Motor2 Output.JogVelocity', sourceEndColumn=1, sourceStartColumn=1, unpackType=0)
Rung 18:
  UPWA(destinationArray=OutputData, destinationStartColumn=101, sourceArray='ClearLink Motor2 Output.AddToPosition', sourceEndColumn=1, sourceStartColumn=1, unpackType=0)
Rung 19:
  PKB(output=OutputData(105), bit1='ClearLink Motor2 Output.OutputReg.Enable', bit2='ClearLink Motor2 Output.OutputReg.AbsolutelMoveFlag', bit3='ClearLink Motor2 Output.OutputReg.HomingFlag', bit4='ClearLink Motor2 Output.OutputReg.LoadPositionData', bit5='ClearLink Motor2 Output.OutputReg.LoadVelocityData', bit6='ClearLink Motor2 Output.OutputReg.SWESTOP', bit7='ClearLink Motor2 Output.OutputReg.ClearAlerts', bit8='ClearLink Motor2 Output.OutputReg.ClearMotorFault')

TASK 'Data Sorting - Motor3'  (Run Every Scan)
// Copies assembly data to/from named controller tags. Do not edit.
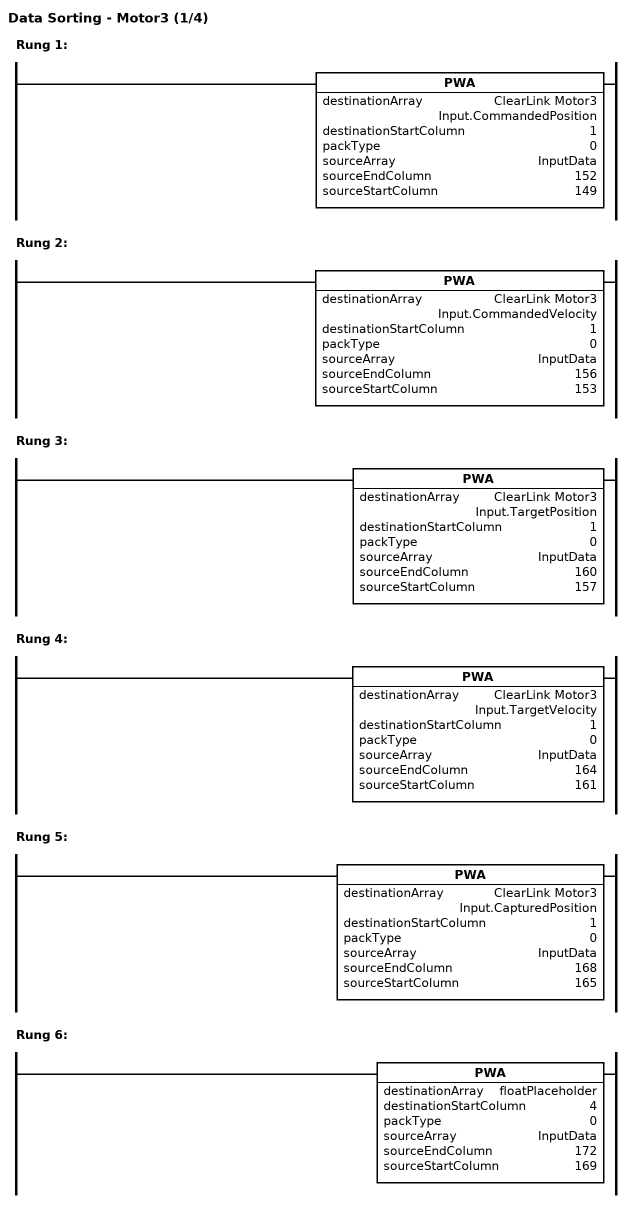
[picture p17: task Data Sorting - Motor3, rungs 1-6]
Rung 1:
  PWA(destinationArray='ClearLink Motor3 Input.CommandedPosition', destinationStartColumn=1, packType=0, sourceArray=InputData, sourceEndColumn=152, sourceStartColumn=149)
Rung 2:
  PWA(destinationArray='ClearLink Motor3 Input.CommandedVelocity', destinationStartColumn=1, packType=0, sourceArray=InputData, sourceEndColumn=156, sourceStartColumn=153)
Rung 3:
  PWA(destinationArray='ClearLink Motor3 Input.TargetPosition', destinationStartColumn=1, packType=0, sourceArray=InputData, sourceEndColumn=160, sourceStartColumn=157)
Rung 4:
  PWA(destinationArray='ClearLink Motor3 Input.TargetVelocity', destinationStartColumn=1, packType=0, sourceArray=InputData, sourceEndColumn=164, sourceStartColumn=161)
Rung 5:
  PWA(destinationArray='ClearLink Motor3 Input.CapturedPosition', destinationStartColumn=1, packType=0, sourceArray=InputData, sourceEndColumn=168, sourceStartColumn=165)
Rung 6:
  PWA(destinationArray=floatPlaceholder, destinationStartColumn=4, packType=0, sourceArray=InputData, sourceEndColumn=172, sourceStartColumn=169)
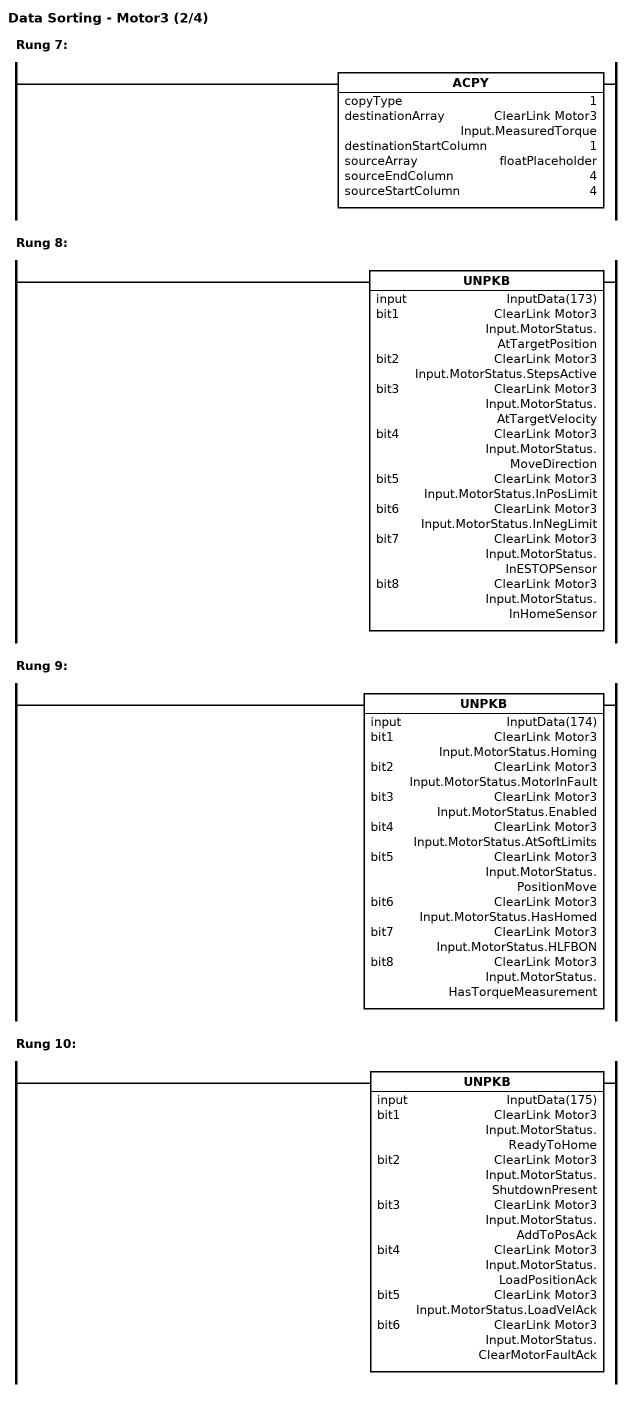
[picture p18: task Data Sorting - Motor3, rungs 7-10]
Rung 7:
  ACPY(copyType=1, destinationArray='ClearLink Motor3 Input.MeasuredTorque', destinationStartColumn=1, sourceArray=floatPlaceholder, sourceEndColumn=4, sourceStartColumn=4)
Rung 8:
  UNPKB(input=InputData(173), bit1='ClearLink Motor3 Input.MotorStatus.AtTargetPosition', bit2='ClearLink Motor3 Input.MotorStatus.StepsActive', bit3='ClearLink Motor3 Input.MotorStatus.AtTargetVelocity', bit4='ClearLink Motor3 Input.MotorStatus.MoveDirection', bit5='ClearLink Motor3 Input.MotorStatus.InPosLimit', bit6='ClearLink Motor3 Input.MotorStatus.InNegLimit', bit7='ClearLink Motor3 Input.MotorStatus.InESTOPSensor', bit8='ClearLink Motor3 Input.MotorStatus.InHomeSensor')
Rung 9:
  UNPKB(input=InputData(174), bit1='ClearLink Motor3 Input.MotorStatus.Homing', bit2='ClearLink Motor3 Input.MotorStatus.MotorInFault', bit3='ClearLink Motor3 Input.MotorStatus.Enabled', bit4='ClearLink Motor3 Input.MotorStatus.AtSoftLimits', bit5='ClearLink Motor3 Input.MotorStatus.PositionMove', bit6='ClearLink Motor3 Input.MotorStatus.HasHomed', bit7='ClearLink Motor3 Input.MotorStatus.HLFBON', bit8='ClearLink Motor3 Input.MotorStatus.HasTorqueMeasurement')
Rung 10:
  UNPKB(input=InputData(175), bit1='ClearLink Motor3 Input.MotorStatus.ReadyToHome', bit2='ClearLink Motor3 Input.MotorStatus.ShutdownPresent', bit3='ClearLink Motor3 Input.MotorStatus.AddToPosAck', bit4='ClearLink Motor3 Input.MotorStatus.LoadPositionAck', bit5='ClearLink Motor3 Input.MotorStatus.LoadVelAck', bit6='ClearLink Motor3 Input.MotorStatus.ClearMotorFaultAck')
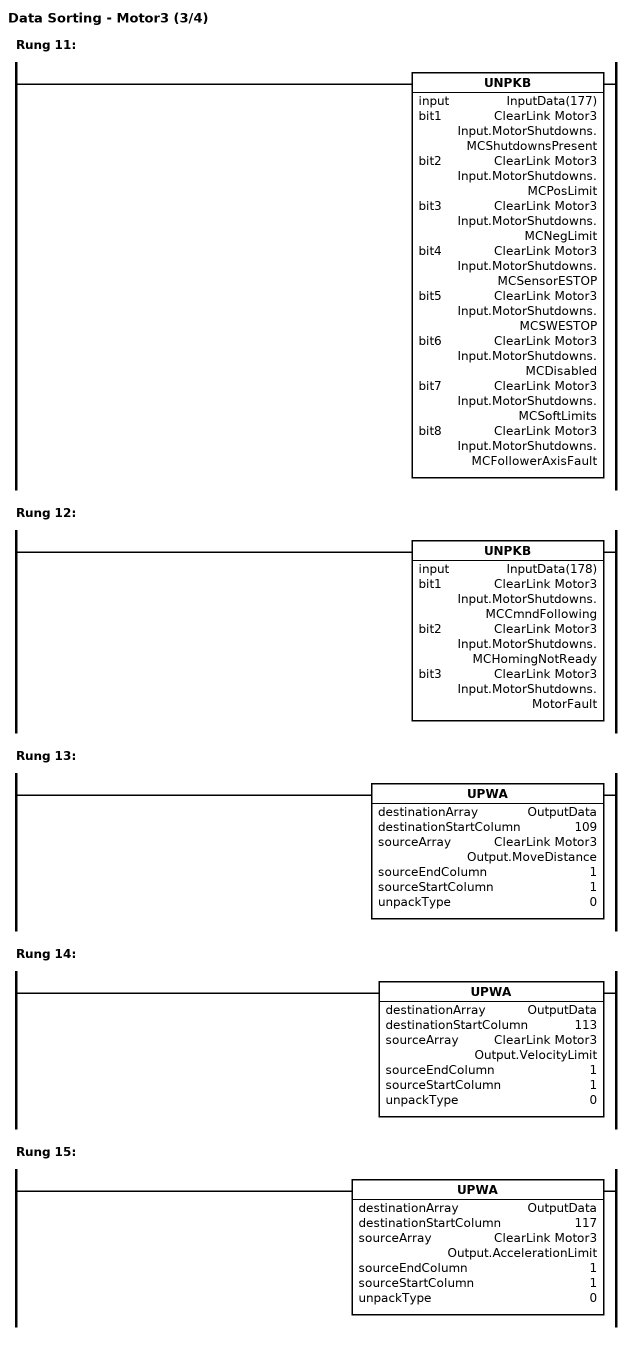
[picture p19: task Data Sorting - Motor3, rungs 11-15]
Rung 11:
  UNPKB(input=InputData(177), bit1='ClearLink Motor3 Input.MotorShutdowns.MCShutdownsPresent', bit2='ClearLink Motor3 Input.MotorShutdowns.MCPosLimit', bit3='ClearLink Motor3 Input.MotorShutdowns.MCNegLimit', bit4='ClearLink Motor3 Input.MotorShutdowns.MCSensorESTOP', bit5='ClearLink Motor3 Input.MotorShutdowns.MCSWESTOP', bit6='ClearLink Motor3 Input.MotorShutdowns.MCDisabled', bit7='ClearLink Motor3 Input.MotorShutdowns.MCSoftLimits', bit8='ClearLink Motor3 Input.MotorShutdowns.MCFollowerAxisFault')
Rung 12:
  UNPKB(input=InputData(178), bit1='ClearLink Motor3 Input.MotorShutdowns.MCCmndFollowing', bit2='ClearLink Motor3 Input.MotorShutdowns.MCHomingNotReady', bit3='ClearLink Motor3 Input.MotorShutdowns.MotorFault')
Rung 13:
  UPWA(destinationArray=OutputData, destinationStartColumn=109, sourceArray='ClearLink Motor3 Output.MoveDistance', sourceEndColumn=1, sourceStartColumn=1, unpackType=0)
Rung 14:
  UPWA(destinationArray=OutputData, destinationStartColumn=113, sourceArray='ClearLink Motor3 Output.VelocityLimit', sourceEndColumn=1, sourceStartColumn=1, unpackType=0)
Rung 15:
  UPWA(destinationArray=OutputData, destinationStartColumn=117, sourceArray='ClearLink Motor3 Output.AccelerationLimit', sourceEndColumn=1, sourceStartColumn=1, unpackType=0)
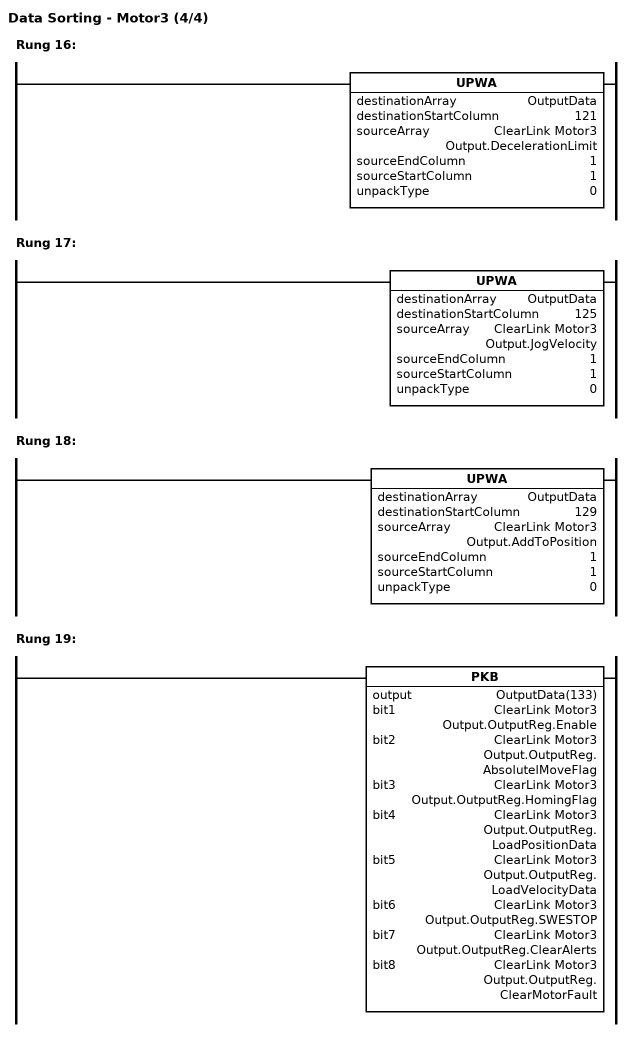
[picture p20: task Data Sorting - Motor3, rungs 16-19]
Rung 16:
  UPWA(destinationArray=OutputData, destinationStartColumn=121, sourceArray='ClearLink Motor3 Output.DecelerationLimit', sourceEndColumn=1, sourceStartColumn=1, unpackType=0)
Rung 17:
  UPWA(destinationArray=OutputData, destinationStartColumn=125, sourceArray='ClearLink Motor3 Output.JogVelocity', sourceEndColumn=1, sourceStartColumn=1, unpackType=0)
Rung 18:
  UPWA(destinationArray=OutputData, destinationStartColumn=129, sourceArray='ClearLink Motor3 Output.AddToPosition', sourceEndColumn=1, sourceStartColumn=1, unpackType=0)
Rung 19:
  PKB(output=OutputData(133), bit1='ClearLink Motor3 Output.OutputReg.Enable', bit2='ClearLink Motor3 Output.OutputReg.AbsolutelMoveFlag', bit3='ClearLink Motor3 Output.OutputReg.HomingFlag', bit4='ClearLink Motor3 Output.OutputReg.LoadPositionData', bit5='ClearLink Motor3 Output.OutputReg.LoadVelocityData', bit6='ClearLink Motor3 Output.OutputReg.SWESTOP', bit7='ClearLink Motor3 Output.OutputReg.ClearAlerts', bit8='ClearLink Motor3 Output.OutputReg.ClearMotorFault')

TASK 'Data Sorting - ASCII'  (Run Every Scan)
// Copies assembly data to/from named controller tags. Do not edit.
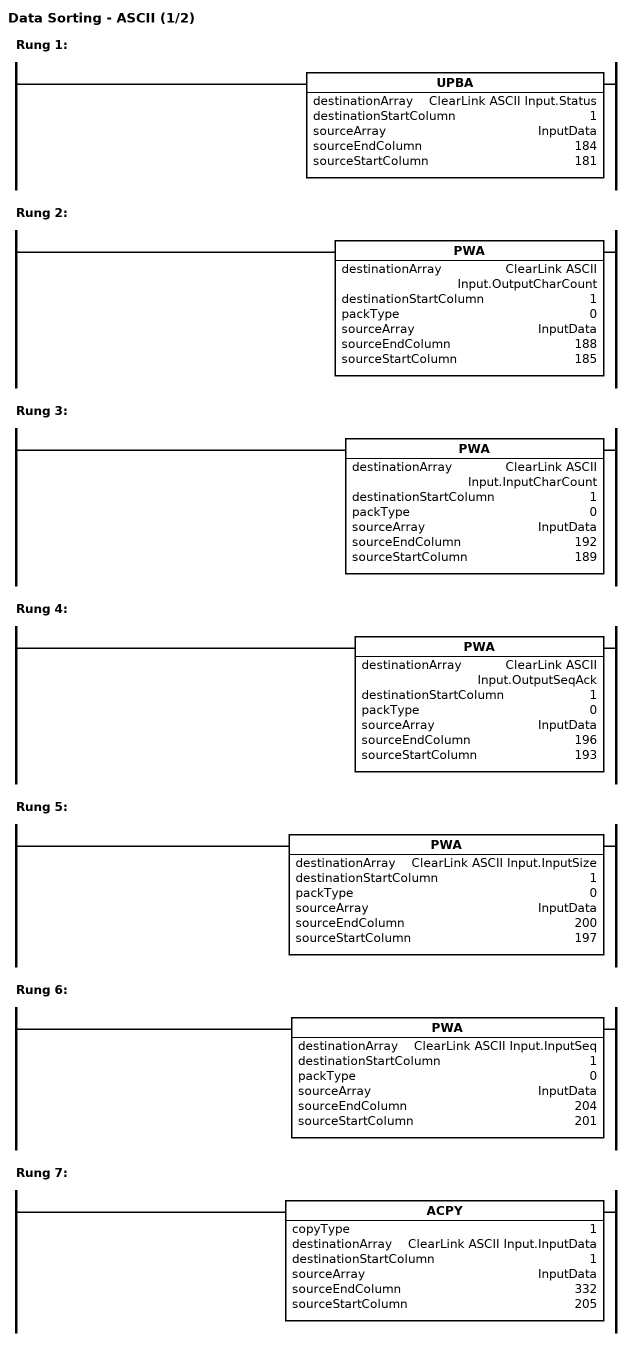
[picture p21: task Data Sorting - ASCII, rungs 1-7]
Rung 1:
  UPBA(destinationArray='ClearLink ASCII Input.Status', destinationStartColumn=1, sourceArray=InputData, sourceEndColumn=184, sourceStartColumn=181)
Rung 2:
  PWA(destinationArray='ClearLink ASCII Input.OutputCharCount', destinationStartColumn=1, packType=0, sourceArray=InputData, sourceEndColumn=188, sourceStartColumn=185)
Rung 3:
  PWA(destinationArray='ClearLink ASCII Input.InputCharCount', destinationStartColumn=1, packType=0, sourceArray=InputData, sourceEndColumn=192, sourceStartColumn=189)
Rung 4:
  PWA(destinationArray='ClearLink ASCII Input.OutputSeqAck', destinationStartColumn=1, packType=0, sourceArray=InputData, sourceEndColumn=196, sourceStartColumn=193)
Rung 5:
  PWA(destinationArray='ClearLink ASCII Input.InputSize', destinationStartColumn=1, packType=0, sourceArray=InputData, sourceEndColumn=200, sourceStartColumn=197)
Rung 6:
  PWA(destinationArray='ClearLink ASCII Input.InputSeq', destinationStartColumn=1, packType=0, sourceArray=InputData, sourceEndColumn=204, sourceStartColumn=201)
Rung 7:
  ACPY(copyType=1, destinationArray='ClearLink ASCII Input.InputData', destinationStartColumn=1, sourceArray=InputData, sourceEndColumn=332, sourceStartColumn=205)
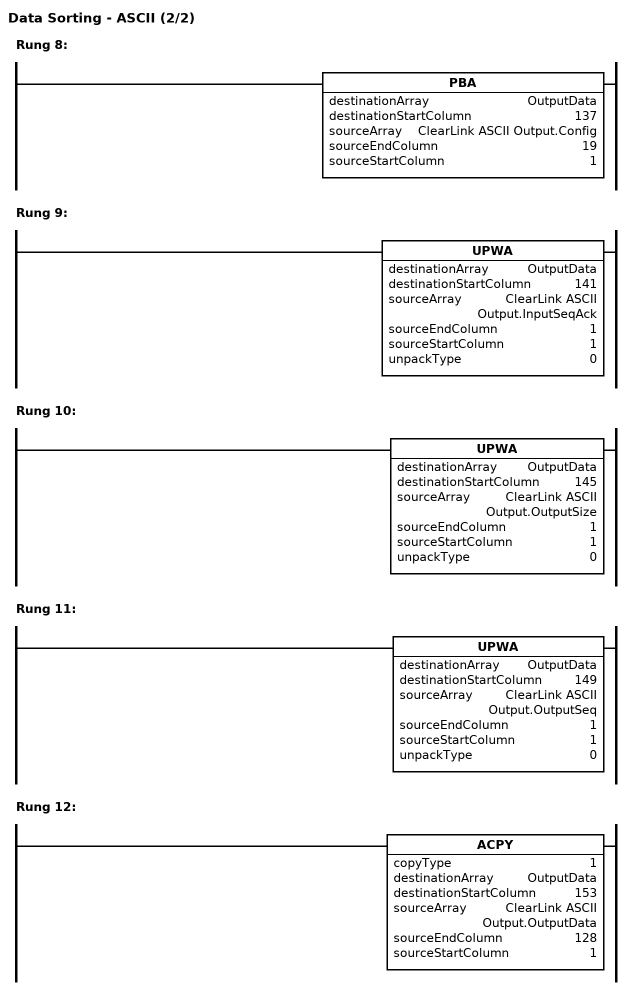
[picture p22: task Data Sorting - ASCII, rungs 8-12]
Rung 8:
  PBA(destinationArray=OutputData, destinationStartColumn=137, sourceArray='ClearLink ASCII Output.Config', sourceEndColumn=19, sourceStartColumn=1)
Rung 9:
  UPWA(destinationArray=OutputData, destinationStartColumn=141, sourceArray='ClearLink ASCII Output.InputSeqAck', sourceEndColumn=1, sourceStartColumn=1, unpackType=0)
Rung 10:
  UPWA(destinationArray=OutputData, destinationStartColumn=145, sourceArray='ClearLink ASCII Output.OutputSize', sourceEndColumn=1, sourceStartColumn=1, unpackType=0)
Rung 11:
  UPWA(destinationArray=OutputData, destinationStartColumn=149, sourceArray='ClearLink ASCII Output.OutputSeq', sourceEndColumn=1, sourceStartColumn=1, unpackType=0)
Rung 12:
  ACPY(copyType=1, destinationArray=OutputData, destinationStartColumn=153, sourceArray='ClearLink ASCII Output.OutputData', sourceEndColumn=128, sourceStartColumn=1)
